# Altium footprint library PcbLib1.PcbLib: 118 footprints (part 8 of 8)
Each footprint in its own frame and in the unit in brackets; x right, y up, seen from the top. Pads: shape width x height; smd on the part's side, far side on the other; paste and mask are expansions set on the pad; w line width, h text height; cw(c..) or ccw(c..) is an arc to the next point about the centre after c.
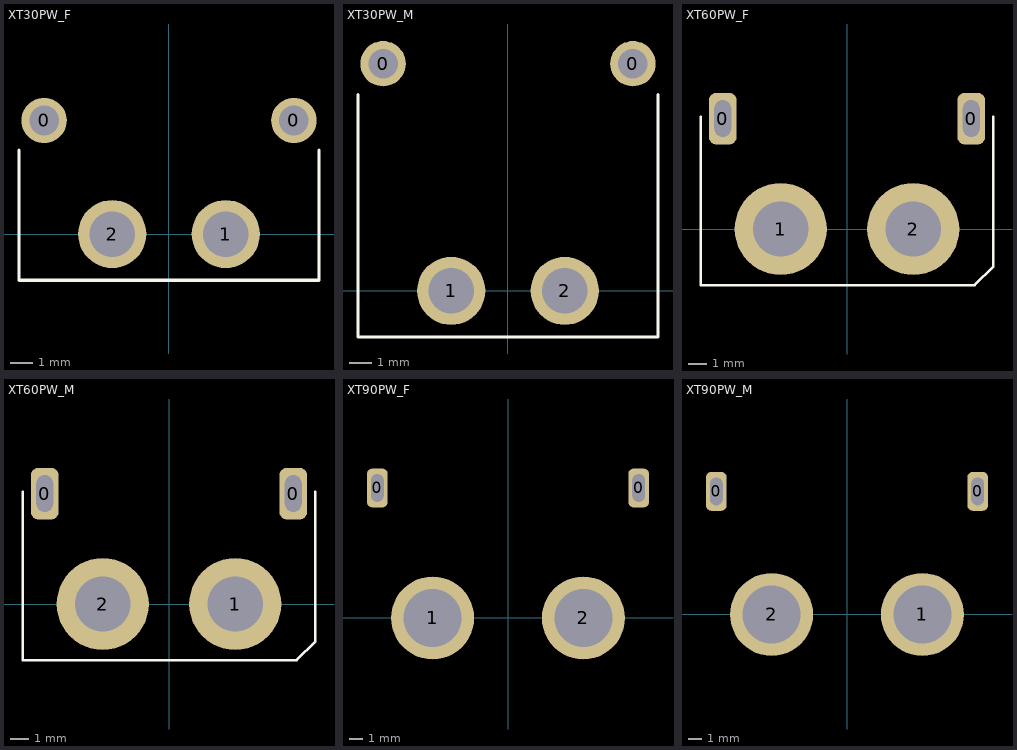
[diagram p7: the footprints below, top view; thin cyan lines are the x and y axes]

## XT30PW_F [mm]
pads (4):
  round 2 hole 1.3: 0(-5.5,5) 0(5.5,5)
  round 3 hole 2: 1(2.5,0) 2(-2.5,0)
Top Overlay:
  lines w0.15: -6.604,3.7 -6.604,-2.032 0,-2.032 6.604,-2.032 6.604,3.7
3D body "XT30PW-F.STEP": height 5, standoff -2, extent -6.65,-1.016 6.65,13.884

## XT30PW_M [mm]
pads (4):
  round 2 hole 1.3: 0(-5.5,10) 0(5.5,10)
  round 3 hole 2: 1(-2.5,0) 2(2.5,0)
Top Overlay:
  lines w0.15: -6.604,8.636 -6.604,-2.032 0,-2.032 6.604,-2.032 6.604,8.636
3D body "XT30PW-M.STEP": height 5, standoff -2, extent -6.65,-0.974 6.65,12.976

## XT60PW_F [mm]
pads (4):
  rrect50% 1.5x2.8 hole 0.9 slot 2 at 90 deg: 0(-6.75,6) 0(6.75,6)
  round 5 hole 3: 1(-3.6,0) 2(3.6,0)
Top Overlay:
  lines w0.15: -7.95,6.096 -7.95,-3.048 -7.442,-3.048 0,-3.048 6.934,-3.048 7.95,-2.032 7.95,6.096
3D body "XT60PW_F.STEP": height 8.45, standoff -2.05, extent -7.95,-2.032 7.95,15.268

## XT60PW_M [mm]
pads (4):
  rrect50% 1.5x2.8 hole 0.9 slot 2 at 90 deg: 0(-6.75,6) 0(6.75,6)
  round 5 hole 3: 1(3.6,0) 2(-3.6,0)
Top Overlay:
  lines w0.15: -7.95,6.096 -7.95,-3.048 -7.442,-3.048 0,-3.048 6.934,-3.048 7.95,-2.032 7.95,6.096
3D body "XT60PW_M.STEP": height 8.45, standoff -2.05, extent -7.95,-2.032 7.95,16.268

## XT90PW_F [mm]
pads (4):
  rrect50% 1.5x2.8 hole 0.9 slot 2 at 90 deg: 0(-9.45,9.4) 0(9.45,9.4)
  round 6 hole 4.2: 1(-5.45,0) 2(5.45,0)
3D body "XT90PW-F.STEP": height 10.1, standoff -2.7, extent -10.35,-2.424 10.35,24.776

## XT90PW_M [mm]
pads (4):
  rrect50% 1.5x2.8 hole 0.9 slot 2 at 90 deg: 0(-9.45,8.9) 0(9.45,8.9)
  round 6 hole 4.2: 1(5.45,0) 2(-5.45,0)
3D body "XT90PW-M.STEP": height 10.1, standoff -2.7, extent -10.35,-2.54 10.35,24.66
